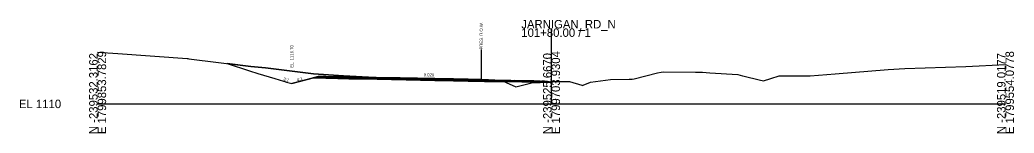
# Model space of a CAD drawing. Extents: x 214513 to 217151, y 214739 to 216780.
# Drawn here: x 216122.7 to 216451.2, y 216238.7 to 216276.2 of the extents above; entities that cross this region are included whole.
import ezdxf

# ---------------------------------------------------------------- set-up
doc = ezdxf.new("R2010")
doc.units = 0
for name, color, linetype in [('CONCEPT - TRANSPORTATION - Roads Text', 7, 'Continuous'), ('DESIGN - CENTERLINE - Proposed', 7, 'Continuous'), ('DESIGN - DRAINAGE - Special Ditches', 7, 'Continuous'), ('DESIGN - EARTHWORK - Shapes', 7, 'Continuous'), ('DESIGN - TRANSPORTATION - Text', 7, 'Continuous'), ('FUNCTIONAL - ROW - Right-of-Way Text', 7, 'Continuous'), ('Section', 7, 'Continuous'), ('SURVEY - DTM GRAPHICS - Triangles', 7, 'Continuous'), ('SURVEY - PROPERTY - ROW Lines', 7, 'Continuous'), ('XSCell', 7, 'Continuous')]:
    doc.layers.add(name, color=color, linetype=linetype)

msp = doc.modelspace()

# ---------------------------------------------------------------- linework, layer by layer
at = {"layer": 'DESIGN - DRAINAGE - Special Ditches'}
for points in [[(216191.21, 216261.75), (216198.56, 216259.3), (216201.32, 216258.46), (216206.91, 216256.8), (216209.75, 216255.89), (216209.9, 216255.84)], [(216221.26, 216257.39), (216217.6, 216256.45), (216212.54, 216255.07)], [(216223.72, 216257.44), (216223.72, 216257.19), (216223.72, 216256.86), (216223.72, 216256.86), (216219.65, 216256.98), (216221.26, 216257.39), (216223.72, 216257.44), (216223.72, 216257.44)], [(216223.72, 216257.44), (216227.68, 216257.36), (216229.91, 216257.32), (216231.41, 216257.29), (216232.53, 216257.27), (216233.44, 216257.25), (216234.13, 216257.24), (216234.76, 216257.23), (216235.34, 216257.22), (216236.04, 216257.21), (216259.8, 216256.74), (216260.88, 216256.72), (216261.85, 216256.7), (216262.74, 216256.69), (216263.58, 216256.67), (216264.39, 216256.65), (216265.19, 216256.64), (216266.01, 216256.62), (216266.87, 216256.6), (216267.8, 216256.58), (216268.67, 216256.56), (216269.64, 216256.54), (216270.76, 216256.51), (216272.1, 216256.47), (216273.89, 216256.44), (216276.25, 216256.4), (216279.61, 216256.33), (216284.89, 216256.22), (216294.59, 216256.02)], [(216294.59, 216256.02), (216294.59, 216255.92), (216284.89, 216256.12), (216279.61, 216256.23), (216276.25, 216256.3), (216273.89, 216256.34), (216272.1, 216256.37), (216270.76, 216256.41), (216269.64, 216256.44), (216268.67, 216256.46), (216267.8, 216256.48), (216266.87, 216256.5), (216266.01, 216256.52), (216265.19, 216256.54), (216264.39, 216256.55), (216263.58, 216256.57), (216262.74, 216256.59), (216261.85, 216256.6), (216260.88, 216256.62), (216259.8, 216256.64), (216236.04, 216257.11), (216235.34, 216257.12), (216234.76, 216257.13), (216234.13, 216257.14), (216233.44, 216257.15), (216232.53, 216257.17), (216231.41, 216257.19), (216229.91, 216257.22), (216227.68, 216257.26), (216223.72, 216257.34), (216223.72, 216257.44), (216227.68, 216257.36), (216229.91, 216257.32), (216231.41, 216257.29), (216232.53, 216257.27), (216233.44, 216257.25), (216234.13, 216257.24), (216234.76, 216257.23), (216235.34, 216257.22), (216236.04, 216257.21), (216259.8, 216256.74), (216260.88, 216256.72), (216261.85, 216256.7), (216262.74, 216256.69), (216263.58, 216256.67), (216264.39, 216256.65), (216265.19, 216256.64), (216266.01, 216256.62), (216266.87, 216256.6), (216267.8, 216256.58), (216268.67, 216256.56), (216269.64, 216256.54), (216270.76, 216256.51), (216272.1, 216256.47), (216273.89, 216256.44), (216276.25, 216256.4), (216279.61, 216256.33), (216284.89, 216256.22), (216294.59, 216256.02)], [(216294.59, 216255.92), (216294.59, 216255.77), (216284.89, 216255.97), (216279.61, 216256.08), (216276.25, 216256.15), (216273.89, 216256.19), (216272.1, 216256.22), (216270.76, 216256.26), (216269.64, 216256.29), (216268.67, 216256.31), (216267.8, 216256.33), (216266.87, 216256.35), (216266.01, 216256.37), (216265.19, 216256.39), (216264.39, 216256.4), (216263.58, 216256.42), (216262.74, 216256.44), (216261.85, 216256.45), (216260.88, 216256.47), (216259.8, 216256.49), (216236.04, 216256.96), (216235.34, 216256.97), (216234.76, 216256.98), (216234.13, 216256.99), (216233.44, 216257), (216232.53, 216257.02), (216231.41, 216257.04), (216229.91, 216257.07), (216227.68, 216257.11), (216223.72, 216257.19), (216223.72, 216257.34), (216227.68, 216257.26), (216229.91, 216257.22), (216231.41, 216257.19), (216232.53, 216257.17), (216233.44, 216257.15), (216234.13, 216257.14), (216234.76, 216257.13), (216235.34, 216257.12), (216236.04, 216257.11), (216259.8, 216256.64), (216260.88, 216256.62), (216261.85, 216256.6), (216262.74, 216256.59), (216263.58, 216256.57), (216264.39, 216256.55), (216265.19, 216256.54), (216266.01, 216256.52), (216266.87, 216256.5), (216267.8, 216256.48), (216268.67, 216256.46), (216269.64, 216256.44), (216270.76, 216256.41), (216272.1, 216256.37), (216273.89, 216256.34), (216276.25, 216256.3), (216279.61, 216256.23), (216284.89, 216256.12), (216294.59, 216255.92)], [(216294.59, 216255.77), (216294.59, 216255.44), (216284.89, 216255.64), (216279.61, 216255.75), (216276.25, 216255.82), (216273.89, 216255.86), (216272.1, 216255.89), (216270.76, 216255.93), (216269.64, 216255.96), (216268.67, 216255.98), (216267.8, 216256), (216266.87, 216256.02), (216266.01, 216256.04), (216265.19, 216256.06), (216264.39, 216256.07), (216263.58, 216256.09), (216262.74, 216256.11), (216261.85, 216256.12), (216260.88, 216256.14), (216259.8, 216256.16), (216236.04, 216256.63), (216235.34, 216256.64), (216234.76, 216256.65), (216234.13, 216256.66), (216233.44, 216256.67), (216232.53, 216256.69), (216231.41, 216256.71), (216229.91, 216256.74), (216227.68, 216256.78), (216223.72, 216256.86), (216223.72, 216257.19), (216227.68, 216257.11), (216229.91, 216257.07), (216231.41, 216257.04), (216232.53, 216257.02), (216233.44, 216257), (216234.13, 216256.99), (216234.76, 216256.98), (216235.34, 216256.97), (216236.04, 216256.96), (216259.8, 216256.49), (216260.88, 216256.47), (216261.85, 216256.45), (216262.74, 216256.44), (216263.58, 216256.42), (216264.39, 216256.4), (216265.19, 216256.39), (216266.01, 216256.37), (216266.87, 216256.35), (216267.8, 216256.33), (216268.67, 216256.31), (216269.64, 216256.29), (216270.76, 216256.26), (216272.1, 216256.22), (216273.89, 216256.19), (216276.25, 216256.15), (216279.61, 216256.08), (216284.89, 216255.97), (216294.59, 216255.77)], [(216209.9, 216255.84), (216210.77, 216255.59), (216212.54, 216255.07)], [(216297.05, 216255.94), (216298.66, 216255.51), (216294.59, 216255.44), (216294.59, 216255.44), (216294.59, 216255.77), (216294.59, 216256.02), (216294.59, 216256.02), (216297.05, 216255.94)], [(216297.05, 216255.94), (216297.87, 216255.72)]]:
    msp.add_lwpolyline(points, dxfattribs=at)
at = {"layer": 'DESIGN - EARTHWORK - Shapes'}
for p, q in [((216221.26, 216257.39), (216219.65, 216256.98)), ((216219.65, 216256.98), (216223.72, 216256.86)), ((216223.72, 216257.44), (216223.18, 216257.43)), ((216223.72, 216257.44), (216227.68, 216257.36)), ((216223.72, 216257.34), (216223.72, 216257.44)), ((216227.68, 216257.36), (216223.72, 216257.44)), ((216223.72, 216257.44), (216223.72, 216257.34)), ((216223.72, 216257.19), (216223.72, 216257.34)), ((216227.68, 216257.26), (216223.72, 216257.34)), ((216223.72, 216257.34), (216223.72, 216257.19)), ((216223.72, 216257.34), (216227.68, 216257.26)), ((216223.72, 216256.86), (216223.72, 216257.19)), ((216227.68, 216257.11), (216223.72, 216257.19)), ((216223.72, 216257.19), (216223.72, 216256.86)), ((216223.72, 216257.19), (216227.68, 216257.11)), ((216229.91, 216257.22), (216227.68, 216257.26)), ((216227.68, 216257.26), (216229.91, 216257.22)), ((216229.91, 216257.07), (216227.68, 216257.11)), ((216227.68, 216257.11), (216229.91, 216257.07)), ((216229.91, 216257.22), (216231.41, 216257.19)), ((216231.41, 216257.19), (216232.53, 216257.17)), ((216232.53, 216257.02), (216233.44, 216257)), ((216234.13, 216256.99), (216233.44, 216257)), ((216233.44, 216257), (216234.13, 216256.99)), ((216234.13, 216257.14), (216234.76, 216257.13)), ((216234.76, 216256.98), (216234.13, 216256.99)), ((216234.13, 216256.99), (216234.76, 216256.98)), ((216235.34, 216257.22), (216234.76, 216257.23)), ((216235.34, 216257.12), (216234.76, 216257.13)), ((216234.76, 216257.13), (216235.34, 216257.12)), ((216236.04, 216257.21), (216235.34, 216257.22)), ((216235.34, 216257.12), (216236.04, 216257.11)), ((216240, 216257.13), (216236.04, 216257.21)), ((216236.04, 216257.11), (216259.8, 216256.64)), ((216236.04, 216256.96), (216259.8, 216256.49)), ((216260.88, 216256.62), (216259.8, 216256.64)), ((216261.85, 216256.6), (216260.88, 216256.62)), ((216262.74, 216256.59), (216261.85, 216256.6)), ((216266.01, 216256.62), (216265.19, 216256.64)), ((216259.8, 216256.49), (216260.88, 216256.47)), ((216263.58, 216256.57), (216264.39, 216256.55)), ((216264.39, 216256.4), (216263.58, 216256.42)), ((216266.01, 216256.52), (216265.19, 216256.54)), ((216265.19, 216256.39), (216266.01, 216256.37)), ((216266.87, 216256.5), (216266.01, 216256.52)), ((216266.01, 216256.37), (216266.87, 216256.35)), ((216267.8, 216256.48), (216266.87, 216256.5)), ((216266.87, 216256.35), (216267.8, 216256.33)), ((216267.8, 216256.48), (216268.67, 216256.46)), ((216267.8, 216256.33), (216268.67, 216256.31)), ((216268.67, 216256.46), (216269.64, 216256.44)), ((216269.64, 216256.29), (216268.67, 216256.31)), ((216268.67, 216256.31), (216269.64, 216256.29)), ((216270.76, 216256.51), (216269.64, 216256.54)), ((216270.76, 216256.41), (216269.64, 216256.44)), ((216269.64, 216256.44), (216270.76, 216256.41)), ((216270.76, 216256.26), (216269.64, 216256.29)), ((216270.76, 216256.41), (216272.1, 216256.37)), ((216272.1, 216256.22), (216270.76, 216256.26)), ((216272.1, 216256.22), (216273.89, 216256.19)), ((216275.2, 216256.42), (216273.89, 216256.44)), ((216276.25, 216256.3), (216273.89, 216256.34)), ((216278.9, 216256.24), (216276.25, 216256.3)), ((216279.61, 216256.08), (216276.25, 216256.15)), ((216282.18, 216256.03), (216278.9, 216256.24)), ((216282.18, 216256.03), (216279.61, 216256.08)), ((216284.89, 216255.64), (216282.95, 216255.68)), ((216292.21, 216255.49), (216284.89, 216255.64)), ((216292.21, 216255.49), (216294.59, 216255.44)), ((216297.86, 216255.72), (216294.59, 216255.61)), ((216294.59, 216255.61), (216294.59, 216255.44)), ((216294.59, 216255.44), (216294.59, 216255.61))]:
    msp.add_line(p, q, dxfattribs=at)
for points in [[(216240, 216257.13), (216229.57, 216257.65), (216219.66, 216258.28), (216203.85, 216260.33), (216198.94, 216260.79), (216191.21, 216261.75)], [(216191.21, 216261.75), (216198.56, 216259.3), (216201.32, 216258.46), (216206.91, 216256.8), (216209.75, 216255.89), (216209.9, 216255.84)], [(216212.54, 216255.07), (216217.6, 216256.45), (216219.65, 216256.98)], [(216219.65, 216256.98), (216221.26, 216257.39), (216222.18, 216257.41), (216223.18, 216257.43), (216223.72, 216257.44)], [(216219.65, 216256.98), (216219.65, 216256.98)], [(216223.18, 216257.43), (216222.18, 216257.41), (216221.26, 216257.39)], [(216223.72, 216256.86), (216227.68, 216256.78), (216229.91, 216256.74), (216231.41, 216256.71), (216232.53, 216256.69), (216233.44, 216256.67), (216234.13, 216256.66), (216234.76, 216256.65), (216235.34, 216256.64), (216236.04, 216256.63), (216259.8, 216256.16), (216260.88, 216256.14), (216261.85, 216256.12), (216262.74, 216256.11), (216263.58, 216256.09), (216264.39, 216256.07), (216265.19, 216256.06), (216266.01, 216256.04), (216266.87, 216256.02), (216267.8, 216256), (216268.67, 216255.98), (216269.64, 216255.96), (216270.76, 216255.93), (216272.1, 216255.89), (216273.89, 216255.86), (216276.25, 216255.82), (216279.61, 216255.75), (216282.95, 216255.68)], [(216227.68, 216257.36), (216229.91, 216257.32), (216231.41, 216257.29)], [(216231.41, 216257.29), (216229.91, 216257.32), (216227.68, 216257.36)], [(216233.44, 216257.15), (216232.53, 216257.17), (216231.41, 216257.19), (216229.91, 216257.22)], [(216233.44, 216257), (216232.53, 216257.02), (216231.41, 216257.04), (216229.91, 216257.07)], [(216229.91, 216257.07), (216231.41, 216257.04), (216232.53, 216257.02)], [(216231.41, 216257.29), (216232.53, 216257.27), (216233.44, 216257.25), (216234.13, 216257.24)], [(216233.44, 216257.25), (216232.53, 216257.27), (216231.41, 216257.29)], [(216232.53, 216257.17), (216233.44, 216257.15), (216234.13, 216257.14)], [(216234.76, 216257.23), (216234.13, 216257.24), (216233.44, 216257.25)], [(216234.76, 216257.13), (216234.13, 216257.14), (216233.44, 216257.15)], [(216234.13, 216257.24), (216234.76, 216257.23), (216235.34, 216257.22)], [(216236.04, 216256.96), (216235.34, 216256.97), (216234.76, 216256.98)], [(216234.76, 216256.98), (216235.34, 216256.97), (216236.04, 216256.96)], [(216235.34, 216257.22), (216236.04, 216257.21), (216240, 216257.13)], [(216259.8, 216256.64), (216236.04, 216257.11), (216235.34, 216257.12)], [(216260.88, 216256.47), (216259.8, 216256.49), (216236.04, 216256.96)], [(216248.32, 216256.97), (216240.38, 216257.11), (216240, 216257.13)], [(216260.88, 216256.72), (216259.8, 216256.74), (216248.32, 216256.97)], [(216259.8, 216256.64), (216260.88, 216256.62), (216261.85, 216256.6)], [(216263.58, 216256.67), (216262.74, 216256.69), (216261.85, 216256.7), (216260.88, 216256.72)], [(216261.85, 216256.6), (216262.74, 216256.59), (216263.58, 216256.57)], [(216265.19, 216256.54), (216264.39, 216256.55), (216263.58, 216256.57), (216262.74, 216256.59)], [(216265.19, 216256.64), (216264.39, 216256.65), (216263.58, 216256.67)], [(216267.8, 216256.58), (216266.87, 216256.6), (216266.01, 216256.62)], [(216209.9, 216255.84), (216210.77, 216255.59), (216212.54, 216255.07)], [(216263.58, 216256.42), (216262.74, 216256.44), (216261.85, 216256.45), (216260.88, 216256.47)], [(216260.88, 216256.47), (216261.85, 216256.45), (216262.74, 216256.44)], [(216262.74, 216256.44), (216263.58, 216256.42), (216264.39, 216256.4), (216265.19, 216256.39)], [(216264.39, 216256.55), (216265.19, 216256.54), (216266.01, 216256.52), (216266.87, 216256.5), (216267.8, 216256.48)], [(216266.87, 216256.35), (216266.01, 216256.37), (216265.19, 216256.39), (216264.39, 216256.4)], [(216268.67, 216256.31), (216267.8, 216256.33), (216266.87, 216256.35)], [(216269.64, 216256.54), (216268.67, 216256.56), (216267.8, 216256.58)], [(216269.64, 216256.44), (216268.67, 216256.46), (216267.8, 216256.48)], [(216269.64, 216256.29), (216270.76, 216256.26), (216272.1, 216256.22)], [(216273.89, 216256.44), (216272.1, 216256.47), (216270.76, 216256.51)], [(216273.89, 216256.34), (216272.1, 216256.37), (216270.76, 216256.41)], [(216272.1, 216256.37), (216273.89, 216256.34), (216276.25, 216256.3), (216278.9, 216256.24)], [(216276.25, 216256.15), (216273.89, 216256.19), (216272.1, 216256.22)], [(216273.89, 216256.19), (216276.25, 216256.15), (216279.61, 216256.08), (216282.18, 216256.03)], [(216278.9, 216256.24), (216277.55, 216256.33), (216276.77, 216256.36), (216275.2, 216256.42)], [(216282.95, 216255.68), (216282.21, 216256.03), (216282.18, 216256.03)], [(216282.95, 216255.68), (216283.34, 216255.5), (216286.58, 216253.99), (216291, 216255.14), (216292.21, 216255.49)], [(216294.59, 216255.61), (216293.85, 216255.59), (216292.45, 216255.56), (216292.21, 216255.49)], [(216294.59, 216255.44), (216298.66, 216255.51), (216297.87, 216255.72), (216297.86, 216255.72)]]:
    msp.add_lwpolyline(points, dxfattribs=at)
at = {"layer": 'FUNCTIONAL - ROW - Right-of-Way Text'}
for p, q in [((216223.18, 216257.43), (216222.18, 216257.41)), ((216259.76, 216256.74), (216257.57, 216256.78)), ((216285.95, 216256.2), (216292.45, 216256.06)), ((216295.11, 216256), (216296.04, 216255.97))]:
    msp.add_line(p, q, dxfattribs=at)
at = {"layer": 'SURVEY - DTM GRAPHICS - Triangles'}
msp.add_lwpolyline([(216148.36, 216265.52), (216155.04, 216265.04), (216177.95, 216263.38), (216178.15, 216263.37), (216178.52, 216263.32), (216198.94, 216260.79), (216203.85, 216260.33), (216219.66, 216258.28), (216229.57, 216257.65), (216240.38, 216257.11), (216255.28, 216256.84), (216274.02, 216256.46), (216276.77, 216256.36), (216277.55, 216256.33), (216282.21, 216256.03), (216283.34, 216255.5), (216286.58, 216253.99), (216291, 216255.14), (216292.45, 216255.56), (216293.85, 216255.59), (216298.65, 216255.75), (216300.61, 216255.73), (216304.27, 216255.73), (216308.35, 216254.52), (216308.53, 216254.47), (216308.77, 216254.57), (216311.27, 216255.57), (216314.48, 216256.05), (216317.8, 216256.46), (216324.03, 216256.53), (216324.94, 216256.54), (216325.6, 216256.7), (216333.35, 216258.65), (216334.54, 216258.85), (216335.25, 216258.99), (216345.95, 216258.88), (216348.24, 216258.86), (216350.65, 216258.7), (216359.92, 216258.09), (216361.47, 216257.71), (216362.01, 216257.55), (216366.91, 216256.31), (216368.37, 216255.97), (216370.76, 216256.77), (216373.62, 216257.64), (216382.75, 216257.66), (216383.86, 216257.68), (216392.07, 216258.36), (216409.57, 216259.77), (216415.12, 216260.06), (216435.29, 216260.74), (216448.36, 216261.37)], dxfattribs=at)
at = {"layer": 'SURVEY - PROPERTY - ROW Lines'}
msp.add_lwpolyline([(216275.12, 216266.42), (216275.12, 216256.42)], dxfattribs=at)
at = {"layer": 'XSCell'}
for p, q in [((216298.36, 216248.36), (216298.36, 216273.36)), ((216148.36, 216248.36), (216298.36, 216248.36)), ((216298.36, 216248.36), (216448.36, 216248.36))]:
    msp.add_line(p, q, dxfattribs=at)

# ---------------------------------------------------------------- texts
at = {"layer": 'CONCEPT - TRANSPORTATION - Roads Text'}
msp.add_text('0.020', height=1, rotation=358.8542, dxfattribs=at).set_placement((216256.1, 216257.51))
at = {"layer": 'DESIGN - CENTERLINE - Proposed'}
for s, rotation, p in [('EL. 1116.70', 90, (216213.04, 216260.35)), ('3:1', 343.0819, (216209.62, 216256.23)), ('4:1', 15.2983, (216214.31, 216255.84))]:
    msp.add_text(s, height=1, rotation=rotation, dxfattribs=at).set_placement(p)
at = {"layer": 'DESIGN - TRANSPORTATION - Text'}
msp.add_text('PRES. R.O.W.', height=1, rotation=90, dxfattribs=at).set_placement((216275.62, 216266.42))
at = {"layer": 'Section'}
msp.add_text('-', height=0.0001, dxfattribs=at).set_placement((216148.36, 216248.36))
at = {"layer": 'XSCell'}
for s, p in [('JARNIGAN_RD_N', (216288.36, 216273.36)), ('101+80.00 / 1', (216288.36, 216270.56)), ('EL 1110', (216122.36, 216246.96))]:
    msp.add_text(s, height=2.8, dxfattribs=at).set_placement(p)
for s, p in [('N -239532.3162', (216148.36, 216238.36)), ('E 1799853.7829', (216151.16, 216238.36)), ('N -239525.6670', (216298.36, 216238.36)), ('E 1799703.9304', (216301.16, 216238.36)), ('N -239519.0177', (216448.36, 216238.36)), ('E 1799554.0778', (216451.16, 216238.36))]:
    msp.add_text(s, height=2.8, rotation=90, dxfattribs=at).set_placement(p)

doc.saveas('drawing.dxf')
